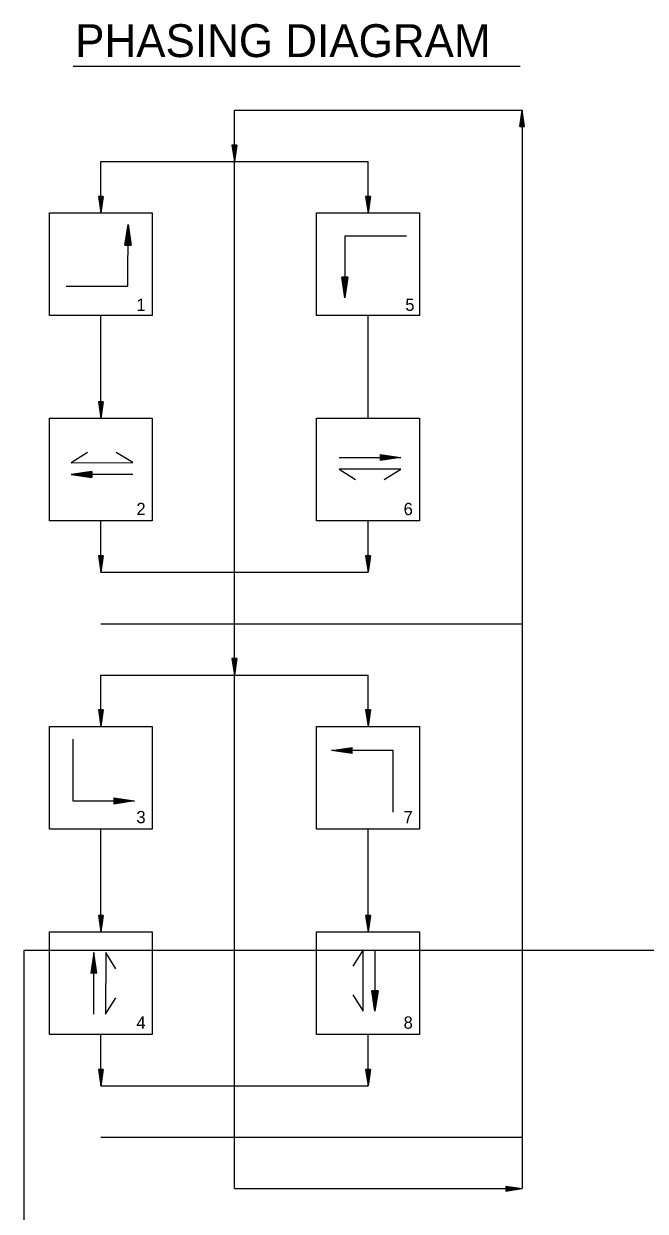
# Model space of a CAD drawing. Extents: x 418532 to 419834, y -565899 to -565285.
# Drawn here: x 418906.3 to 419057.5, y -565574.5 to -565285.5 of the extents above; entities that cross this region are included whole.
import ezdxf

# ---------------------------------------------------------------- set-up
doc = ezdxf.new("R2010")
doc.units = 0
doc.layers.add('Level 57', color=7, linetype='Continuous')
doc.layers.add('Template', color=7, linetype='Continuous')

msp = doc.modelspace()

# ---------------------------------------------------------------- linework, layer by layer
at = {"layer": 'Level 57'}
for p, q in [((418918.38, -565295.76), (419027.05, -565295.76)), ((418957.57, -565568.98), (418957.57, -565306.48)), ((418957.57, -565306.48), (419027.57, -565306.48)), ((419026.97, -565310.48), (419027.57, -565306.48)), ((419027.07, -565310.48), (419027.57, -565307.15)), ((419027.18, -565310.48), (419027.57, -565307.83)), ((419027.28, -565310.48), (419027.57, -565308.5)), ((419027.57, -565306.48), (419027.57, -565568.98)), ((419028.17, -565310.48), (419027.57, -565306.48)), ((419028.07, -565310.48), (419027.57, -565307.15)), ((419027.97, -565310.48), (419027.57, -565307.83)), ((419027.87, -565310.48), (419027.57, -565308.5)), ((419026.97, -565310.48), (419028.17, -565310.48)), ((419027.38, -565310.48), (419027.57, -565309.18)), ((419027.48, -565310.48), (419027.57, -565309.85)), ((419027.77, -565310.48), (419027.57, -565309.18)), ((419027.67, -565310.48), (419027.57, -565309.85)), ((418956.97, -565314.98), (418957.57, -565318.98)), ((418958.17, -565314.98), (418956.97, -565314.98)), ((418957.07, -565314.98), (418957.57, -565318.31)), ((418957.18, -565314.98), (418957.57, -565317.62)), ((418957.28, -565314.98), (418957.57, -565316.96)), ((418957.38, -565314.98), (418957.57, -565316.28)), ((418957.48, -565314.98), (418957.57, -565315.61)), ((418958.17, -565314.98), (418957.57, -565318.98)), ((418957.77, -565314.98), (418957.57, -565316.28)), ((418957.97, -565314.98), (418957.57, -565317.62)), ((418958.07, -565314.98), (418957.57, -565318.31)), ((418957.87, -565314.98), (418957.57, -565316.96)), ((418957.67, -565314.98), (418957.57, -565315.61)), ((418925.07, -565331.48), (418925.07, -565318.98)), ((418925.07, -565318.98), (418990.07, -565318.98)), ((418990.07, -565331.48), (418990.07, -565318.98)), ((418924.47, -565327.48), (418925.07, -565331.48)), ((418925.67, -565327.48), (418924.47, -565327.48)), ((418924.57, -565327.48), (418925.07, -565330.81)), ((418924.68, -565327.48), (418925.07, -565330.12)), ((418924.78, -565327.48), (418925.07, -565329.46)), ((418924.88, -565327.48), (418925.07, -565328.78)), ((418924.98, -565327.48), (418925.07, -565328.11)), ((418925.67, -565327.48), (418925.07, -565331.48)), ((418925.27, -565327.48), (418925.07, -565328.78)), ((418925.47, -565327.48), (418925.07, -565330.12)), ((418925.57, -565327.48), (418925.07, -565330.81)), ((418925.37, -565327.48), (418925.07, -565329.46)), ((418925.17, -565327.48), (418925.07, -565328.11)), ((418989.47, -565327.48), (418990.07, -565331.48)), ((418990.67, -565327.48), (418989.47, -565327.48)), ((418989.57, -565327.48), (418990.07, -565330.81)), ((418989.68, -565327.48), (418990.07, -565330.12)), ((418989.78, -565327.48), (418990.07, -565329.46)), ((418989.88, -565327.48), (418990.07, -565328.78)), ((418989.98, -565327.48), (418990.07, -565328.11)), ((418990.67, -565327.48), (418990.07, -565331.48)), ((418990.27, -565327.48), (418990.07, -565328.78)), ((418990.47, -565327.48), (418990.07, -565330.12)), ((418990.57, -565327.48), (418990.07, -565330.81)), ((418990.37, -565327.48), (418990.07, -565329.46)), ((418990.17, -565327.48), (418990.07, -565328.11)), ((418930.93, -565339.35), (418931.69, -565334.35)), ((418931.67, -565349.35), (418931.69, -565334.35)), ((418931.69, -565334.35), (418932.43, -565339.35)), ((418931.69, -565335.19), (418931.06, -565339.35)), ((418931.19, -565339.35), (418931.69, -565336.05)), ((418931.69, -565336.88), (418931.31, -565339.35)), ((418932.31, -565339.35), (418931.69, -565335.19)), ((418931.69, -565336.05), (418932.18, -565339.35)), ((418932.06, -565339.35), (418931.69, -565336.88)), ((418999.43, -565337.16), (418984.43, -565337.16)), ((418984.43, -565337.16), (418984.43, -565352.16)), ((418930.93, -565339.35), (418932.43, -565339.35)), ((418931.44, -565339.35), (418931.69, -565337.73)), ((418931.68, -565338.56), (418931.57, -565339.35)), ((418931.8, -565339.35), (418931.68, -565338.56)), ((418931.69, -565337.73), (418931.93, -565339.35)), ((418984.43, -565352.16), (418983.68, -565347.16)), ((418985.18, -565347.16), (418983.68, -565347.16)), ((418983.81, -565347.16), (418984.43, -565351.33)), ((418984.43, -565350.47), (418983.93, -565347.16)), ((418984.06, -565347.16), (418984.43, -565349.63)), ((418984.43, -565348.79), (418984.19, -565347.16)), ((418984.31, -565347.16), (418984.43, -565347.95)), ((418984.43, -565347.95), (418984.55, -565347.16)), ((418984.67, -565347.16), (418984.43, -565348.79)), ((418984.43, -565349.63), (418984.8, -565347.16)), ((418984.93, -565347.16), (418984.43, -565350.47)), ((418984.43, -565351.33), (418985.06, -565347.16)), ((418985.18, -565347.16), (418984.43, -565352.16)), ((418916.67, -565349.34), (418931.67, -565349.35)), ((418925.07, -565381.48), (418925.07, -565356.48)), ((418990.07, -565381.48), (418990.07, -565356.48)), ((418924.47, -565377.48), (418925.07, -565381.48)), ((418925.67, -565377.48), (418924.47, -565377.48)), ((418924.57, -565377.48), (418925.07, -565380.81)), ((418924.68, -565377.48), (418925.07, -565380.12)), ((418924.78, -565377.48), (418925.07, -565379.46)), ((418924.88, -565377.48), (418925.07, -565378.78)), ((418924.98, -565377.48), (418925.07, -565378.11)), ((418925.67, -565377.48), (418925.07, -565381.48)), ((418925.27, -565377.48), (418925.07, -565378.78)), ((418925.47, -565377.48), (418925.07, -565380.12)), ((418925.57, -565377.48), (418925.07, -565380.81)), ((418925.37, -565377.48), (418925.07, -565379.46)), ((418925.17, -565377.48), (418925.07, -565378.11)), ((418983.01, -565391.03), (418998.01, -565391.04)), ((418993.01, -565390.29), (418998.01, -565391.04)), ((418993.01, -565390.29), (418993.01, -565391.79)), ((418997.18, -565391.04), (418993.01, -565390.41)), ((418993.01, -565390.54), (418996.32, -565391.04)), ((418995.48, -565391.04), (418993.01, -565390.66)), ((418993.01, -565390.79), (418994.64, -565391.04)), ((418993.8, -565391.04), (418993.01, -565390.92)), ((418998.01, -565391.04), (418993.01, -565391.79)), ((418993.01, -565391.66), (418997.18, -565391.04)), ((418996.32, -565391.04), (418993.01, -565391.53)), ((418993.01, -565391.41), (418995.48, -565391.04)), ((418994.64, -565391.04), (418993.01, -565391.28)), ((418993.01, -565391.15), (418993.8, -565391.04)), ((418922.85, -565394.42), (418917.85, -565395.18)), ((418932.85, -565395.14), (418917.85, -565395.18)), ((418917.85, -565395.18), (418922.85, -565395.92)), ((418918.68, -565395.18), (418922.85, -565394.54)), ((418922.85, -565395.79), (418918.68, -565395.18)), ((418922.85, -565394.67), (418919.54, -565395.18)), ((418919.54, -565395.18), (418922.85, -565395.67)), ((418920.38, -565395.18), (418922.85, -565394.8)), ((418922.85, -565395.54), (418920.38, -565395.18)), ((418922.85, -565394.93), (418921.22, -565395.17)), ((418921.22, -565395.17), (418922.85, -565395.41)), ((418922.06, -565395.17), (418922.85, -565395.05)), ((418922.85, -565395.29), (418922.06, -565395.17)), ((418922.85, -565394.42), (418922.85, -565395.92)), ((418925.07, -565418.98), (418925.07, -565406.48)), ((418990.07, -565418.98), (418990.07, -565406.48)), ((418990.07, -565418.98), (418990.07, -565406.48)), ((418924.47, -565414.98), (418925.07, -565418.98)), ((418925.67, -565414.98), (418924.47, -565414.98)), ((418924.57, -565414.98), (418925.07, -565418.31)), ((418924.68, -565414.98), (418925.07, -565417.62)), ((418924.78, -565414.98), (418925.07, -565416.96)), ((418924.88, -565414.98), (418925.07, -565416.28)), ((418924.98, -565414.98), (418925.07, -565415.61)), ((418925.67, -565414.98), (418925.07, -565418.98)), ((418925.27, -565414.98), (418925.07, -565416.28)), ((418925.47, -565414.98), (418925.07, -565417.62)), ((418925.57, -565414.98), (418925.07, -565418.31)), ((418925.37, -565414.98), (418925.07, -565416.96)), ((418925.17, -565414.98), (418925.07, -565415.61)), ((418989.47, -565414.98), (418990.07, -565418.98)), ((418990.67, -565414.98), (418989.47, -565414.98)), ((418989.47, -565414.98), (418990.07, -565418.98)), ((418990.67, -565414.98), (418989.47, -565414.98)), ((418989.57, -565414.98), (418990.07, -565418.31)), ((418989.57, -565414.98), (418990.07, -565418.31)), ((418989.68, -565414.98), (418990.07, -565417.62)), ((418989.68, -565414.98), (418990.07, -565417.62)), ((418989.78, -565414.98), (418990.07, -565416.96)), ((418989.78, -565414.98), (418990.07, -565416.96)), ((418989.88, -565414.98), (418990.07, -565416.28)), ((418989.88, -565414.98), (418990.07, -565416.28)), ((418989.98, -565414.98), (418990.07, -565415.61)), ((418989.98, -565414.98), (418990.07, -565415.61)), ((418990.67, -565414.98), (418990.07, -565418.98)), ((418990.27, -565414.98), (418990.07, -565416.28)), ((418990.47, -565414.98), (418990.07, -565417.62)), ((418990.57, -565414.98), (418990.07, -565418.31)), ((418990.37, -565414.98), (418990.07, -565416.96)), ((418990.17, -565414.98), (418990.07, -565415.61)), ((418990.67, -565414.98), (418990.07, -565418.98)), ((418990.27, -565414.98), (418990.07, -565416.28)), ((418990.47, -565414.98), (418990.07, -565417.62)), ((418990.57, -565414.98), (418990.07, -565418.31)), ((418990.37, -565414.98), (418990.07, -565416.96)), ((418990.17, -565414.98), (418990.07, -565415.61)), ((418925.07, -565418.98), (418990.07, -565418.98)), ((418925.07, -565431.48), (419027.57, -565431.48)), ((418956.97, -565439.98), (418957.57, -565443.98)), ((418958.17, -565439.98), (418956.97, -565439.98)), ((418957.07, -565439.98), (418957.57, -565443.31)), ((418957.18, -565439.98), (418957.57, -565442.62)), ((418957.28, -565439.98), (418957.57, -565441.96)), ((418957.38, -565439.98), (418957.57, -565441.28)), ((418957.48, -565439.98), (418957.57, -565440.61)), ((418958.17, -565439.98), (418957.57, -565443.98)), ((418957.77, -565439.98), (418957.57, -565441.28)), ((418957.97, -565439.98), (418957.57, -565442.62)), ((418958.07, -565439.98), (418957.57, -565443.31)), ((418957.87, -565439.98), (418957.57, -565441.96)), ((418957.67, -565439.98), (418957.57, -565440.61)), ((418925.07, -565443.98), (418990.07, -565443.98)), ((418925.07, -565456.48), (418925.07, -565443.98)), ((418990.07, -565456.48), (418990.07, -565443.98)), ((418924.47, -565452.48), (418925.07, -565456.48)), ((418925.67, -565452.48), (418924.47, -565452.48)), ((418924.57, -565452.48), (418925.07, -565455.81)), ((418924.68, -565452.48), (418925.07, -565455.12)), ((418924.78, -565452.48), (418925.07, -565454.46)), ((418924.88, -565452.48), (418925.07, -565453.78)), ((418924.98, -565452.48), (418925.07, -565453.11)), ((418925.67, -565452.48), (418925.07, -565456.48)), ((418925.27, -565452.48), (418925.07, -565453.78)), ((418925.47, -565452.48), (418925.07, -565455.12)), ((418925.57, -565452.48), (418925.07, -565455.81)), ((418925.37, -565452.48), (418925.07, -565454.46)), ((418925.17, -565452.48), (418925.07, -565453.11)), ((418989.47, -565452.48), (418990.07, -565456.48)), ((418990.67, -565452.48), (418989.47, -565452.48)), ((418989.57, -565452.48), (418990.07, -565455.81)), ((418989.68, -565452.48), (418990.07, -565455.12)), ((418989.78, -565452.48), (418990.07, -565454.46)), ((418989.88, -565452.48), (418990.07, -565453.78)), ((418989.98, -565452.48), (418990.07, -565453.11)), ((418990.67, -565452.48), (418990.07, -565456.48)), ((418990.27, -565452.48), (418990.07, -565453.78)), ((418990.47, -565452.48), (418990.07, -565455.12)), ((418990.57, -565452.48), (418990.07, -565455.81)), ((418990.37, -565452.48), (418990.07, -565454.46)), ((418990.17, -565452.48), (418990.07, -565453.11)), ((418918.26, -565459.62), (418918.26, -565474.62)), ((418981.18, -565462.35), (418986.18, -565461.6)), ((418986.18, -565461.73), (418982.01, -565462.35)), ((418982.87, -565462.35), (418986.18, -565461.86)), ((418986.18, -565463.1), (418986.18, -565461.6)), ((418996.18, -565462.35), (418981.18, -565462.35)), ((418986.18, -565463.1), (418981.18, -565462.35)), ((418982.01, -565462.35), (418986.18, -565462.98)), ((418986.18, -565462.85), (418982.87, -565462.35)), ((418986.18, -565461.98), (418983.7, -565462.35)), ((418983.7, -565462.35), (418986.18, -565462.73)), ((418984.55, -565462.35), (418986.18, -565462.11)), ((418986.18, -565462.6), (418984.55, -565462.35)), ((418986.18, -565462.24), (418985.39, -565462.35)), ((418985.39, -565462.35), (418986.18, -565462.47)), ((418996.18, -565477.35), (418996.18, -565462.35)), ((418918.26, -565474.62), (418933.26, -565474.62)), ((418928.26, -565473.87), (418933.26, -565474.62)), ((418928.26, -565473.87), (418928.26, -565475.37)), ((418932.42, -565474.62), (418928.26, -565474)), ((418928.26, -565474.12), (418931.56, -565474.62)), ((418930.73, -565474.62), (418928.26, -565474.25)), ((418928.26, -565474.38), (418929.88, -565474.62)), ((418929.05, -565474.62), (418928.26, -565474.5)), ((418933.26, -565474.62), (418928.26, -565475.37)), ((418928.26, -565475.25), (418932.42, -565474.62)), ((418931.56, -565474.62), (418928.26, -565475.12)), ((418928.26, -565474.99), (418930.73, -565474.62)), ((418929.88, -565474.62), (418928.26, -565474.87)), ((418928.26, -565474.74), (418929.05, -565474.62)), ((418925.07, -565506.48), (418925.07, -565481.48)), ((418990.07, -565506.48), (418990.07, -565481.48)), ((418924.47, -565502.48), (418925.07, -565506.48)), ((418925.67, -565502.48), (418924.47, -565502.48)), ((418924.57, -565502.48), (418925.07, -565505.81)), ((418924.68, -565502.48), (418925.07, -565505.12)), ((418924.78, -565502.48), (418925.07, -565504.46)), ((418924.88, -565502.48), (418925.07, -565503.78)), ((418924.98, -565502.48), (418925.07, -565503.11)), ((418925.67, -565502.48), (418925.07, -565506.48)), ((418925.27, -565502.48), (418925.07, -565503.78)), ((418925.47, -565502.48), (418925.07, -565505.12)), ((418925.57, -565502.48), (418925.07, -565505.81)), ((418925.37, -565502.48), (418925.07, -565504.46)), ((418925.17, -565502.48), (418925.07, -565503.11)), ((418989.47, -565502.48), (418990.07, -565506.48)), ((418990.67, -565502.48), (418989.47, -565502.48)), ((418989.57, -565502.48), (418990.07, -565505.81)), ((418989.68, -565502.48), (418990.07, -565505.12)), ((418989.78, -565502.48), (418990.07, -565504.46)), ((418989.88, -565502.48), (418990.07, -565503.78)), ((418989.98, -565502.48), (418990.07, -565503.11)), ((418990.67, -565502.48), (418990.07, -565506.48)), ((418990.27, -565502.48), (418990.07, -565503.78)), ((418990.47, -565502.48), (418990.07, -565505.12)), ((418990.57, -565502.48), (418990.07, -565505.81)), ((418990.37, -565502.48), (418990.07, -565504.46)), ((418990.17, -565502.48), (418990.07, -565503.11)), ((418991.75, -565510.82), (418991.74, -565525.82)), ((418923.38, -565511.51), (418922.63, -565516.51)), ((418922.75, -565516.51), (418923.38, -565512.34)), ((418923.38, -565513.2), (418922.88, -565516.51)), ((418923.36, -565526.51), (418923.38, -565511.51)), ((418924.13, -565516.51), (418923.38, -565511.51)), ((418923.38, -565512.34), (418924, -565516.51)), ((418923.87, -565516.51), (418923.38, -565513.2)), ((418924.13, -565516.51), (418922.63, -565516.51)), ((418923, -565516.51), (418923.38, -565514.04)), ((418923.38, -565514.88), (418923.13, -565516.51)), ((418923.26, -565516.51), (418923.38, -565515.72)), ((418923.38, -565514.04), (418923.75, -565516.51)), ((418923.62, -565516.51), (418923.38, -565514.88)), ((418923.38, -565515.72), (418923.49, -565516.51)), ((418991.74, -565525.82), (418991, -565520.82)), ((418992.5, -565520.82), (418991, -565520.82)), ((418991.12, -565520.82), (418991.74, -565524.98)), ((418991.74, -565524.12), (418991.25, -565520.82)), ((418991.37, -565520.82), (418991.75, -565523.29)), ((418991.75, -565522.44), (418991.5, -565520.82)), ((418991.63, -565520.82), (418991.75, -565521.61)), ((418992.24, -565520.82), (418991.74, -565524.12)), ((418991.74, -565524.98), (418992.37, -565520.82)), ((418992.5, -565520.82), (418991.74, -565525.82)), ((418991.75, -565521.61), (418991.86, -565520.82)), ((418991.99, -565520.82), (418991.75, -565522.44)), ((418991.75, -565523.29), (418992.12, -565520.82)), ((418925.07, -565543.98), (418925.07, -565531.48)), ((418990.07, -565543.98), (418990.07, -565531.48)), ((418924.47, -565539.98), (418925.07, -565543.98)), ((418925.67, -565539.98), (418924.47, -565539.98)), ((418924.57, -565539.98), (418925.07, -565543.31)), ((418924.68, -565539.98), (418925.07, -565542.62)), ((418924.78, -565539.98), (418925.07, -565541.96)), ((418924.88, -565539.98), (418925.07, -565541.28)), ((418924.98, -565539.98), (418925.07, -565540.61)), ((418925.67, -565539.98), (418925.07, -565543.98)), ((418925.27, -565539.98), (418925.07, -565541.28)), ((418925.47, -565539.98), (418925.07, -565542.62)), ((418925.57, -565539.98), (418925.07, -565543.31)), ((418925.37, -565539.98), (418925.07, -565541.96)), ((418925.17, -565539.98), (418925.07, -565540.61)), ((418989.47, -565539.98), (418990.07, -565543.98)), ((418990.67, -565539.98), (418989.47, -565539.98)), ((418989.57, -565539.98), (418990.07, -565543.31)), ((418989.68, -565539.98), (418990.07, -565542.62)), ((418989.78, -565539.98), (418990.07, -565541.96)), ((418989.88, -565539.98), (418990.07, -565541.28)), ((418989.98, -565539.98), (418990.07, -565540.61)), ((418990.67, -565539.98), (418990.07, -565543.98)), ((418990.27, -565539.98), (418990.07, -565541.28)), ((418990.47, -565539.98), (418990.07, -565542.62)), ((418990.57, -565539.98), (418990.07, -565543.31)), ((418990.37, -565539.98), (418990.07, -565541.96)), ((418990.17, -565539.98), (418990.07, -565540.61)), ((418925.07, -565543.98), (418990.07, -565543.98)), ((418925.07, -565556.48), (419027.57, -565556.48)), ((419023.57, -565568.38), (419027.57, -565568.98)), ((419023.57, -565568.38), (419023.57, -565569.58)), ((419023.57, -565568.48), (419026.91, -565568.98)), ((419023.57, -565568.58), (419026.22, -565568.98)), ((419023.57, -565568.68), (419025.55, -565568.98)), ((419023.57, -565568.78), (419024.87, -565568.98)), ((418957.57, -565568.98), (419027.57, -565568.98)), ((419023.57, -565568.88), (419024.21, -565568.98)), ((419023.57, -565569.58), (419027.57, -565568.98)), ((419023.57, -565569.17), (419024.87, -565568.98)), ((419023.57, -565569.38), (419026.22, -565568.98)), ((419023.57, -565569.48), (419026.91, -565568.98)), ((419023.57, -565569.28), (419025.55, -565568.98)), ((419023.57, -565569.07), (419024.21, -565568.98))]:
    msp.add_line(p, q, dxfattribs=at)
for points in [[(418912.57, -565331.48), (418937.57, -565331.48), (418937.57, -565356.48), (418912.57, -565356.48)], [(418977.57, -565331.48), (419002.57, -565331.48), (419002.57, -565356.48), (418977.57, -565356.48)], [(418912.57, -565381.48), (418937.57, -565381.48), (418937.57, -565406.48), (418912.57, -565406.48)], [(418977.57, -565381.48), (419002.57, -565381.48), (419002.57, -565406.48), (418977.57, -565406.48)], [(418912.57, -565456.48), (418937.57, -565456.48), (418937.57, -565481.48), (418912.57, -565481.48)], [(418977.57, -565456.48), (419002.57, -565456.48), (419002.57, -565481.48), (418977.57, -565481.48)], [(418912.57, -565506.48), (418937.57, -565506.48), (418937.57, -565531.48), (418912.57, -565531.48)], [(418977.57, -565506.48), (419002.57, -565506.48), (419002.57, -565531.48), (418977.57, -565531.48)]]:
    msp.add_lwpolyline(points, close=True, dxfattribs=at)
for points in [[(418921.83, -565389.8), (418917.84, -565392.31), (418932.84, -565392.26), (418928.83, -565389.78)], [(418994.01, -565396.41), (418998.01, -565393.91), (418983.01, -565393.91), (418987.01, -565396.41)], [(418986.37, -565521.82), (418988.87, -565525.82), (418988.87, -565510.82), (418986.37, -565514.82)], [(418928.75, -565515.52), (418926.26, -565511.51), (418926.24, -565526.51), (418928.74, -565522.52)]]:
    msp.add_lwpolyline(points, dxfattribs=at)
at = {"layer": 'Template'}
msp.add_lwpolyline([(419214.2, -565511.02), (418906.32, -565511.02), (418906.32, -565641.34), (419214.2, -565641.34)], close=True, dxfattribs=at)

# ---------------------------------------------------------------- texts
at = {"layer": 'Level 57'}
for s, height, p in [('PHASING DIAGRAM', 8, (418918.82, -565293.58)), ('1', 3, (418933.73, -565355.34)), ('5', 3, (418999.14, -565355.34)), ('2', 3, (418933.73, -565405.06)), ('6', 3, (418998.73, -565405.06)), ('3', 3, (418933.73, -565480.06)), ('7', 3, (418998.73, -565480.06)), ('4', 3, (418933.73, -565530.06)), ('8', 3, (418998.73, -565530.06))]:
    msp.add_text(s, height=height, dxfattribs=at).set_placement(p)

doc.saveas('drawing.dxf')
